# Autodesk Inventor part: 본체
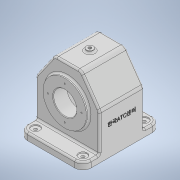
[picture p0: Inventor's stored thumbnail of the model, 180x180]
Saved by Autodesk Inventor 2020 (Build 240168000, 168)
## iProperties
Created: 2022-12
Part Number: 본체
Material: 일반
Document SubType Name: Modeling
Designer: 1강의실14
Density: 1 g/cm^3
Appearance: 기본값
Mass: 347.033 g
Surface Area: 1065.53 cm^2
Volume: 347.033 cm^3
Author: 1강의실14
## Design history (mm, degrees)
sketch "스케치1"
  geometry: L1 (-55, 67)-(55, 67); L2 (55, 67)-(55, -67); L3 (55, -67)-(-55, -67); L4 (-55, -67)-(-55, 67); L5 (-55, 67)-(55, -67); L6 (55, 67)-(-55, -67); 1 further point
  constraints: 12 end point, 2 midpoint, 2 parallel, 1 horizontal, 1 perpendicular
  dimensions: "d0" = 110 distance of L2.end L3.end; "d1" = 134 distance of L1.end L2.end
extrude "돌출1" new body sketch "스케치1" distance "d2" = 12; taper "d3" = 0 deg
sketch "스케치2"
  geometry: L1 (-55, 12)-(55, 12) reference; L2 (55, 12)-(-55, 12) reference; L3 (-55, 0)-(55, 0) reference; L4 (23.491, 122)-(55, 77); L5 (55, 77)-(55, 12); L6 (-55, 77)-(-55, 12); L7 (23.491, 122)-(-23.491, 122); L8 (-23.491, 122)-(-55, 77); 2 further points
  constraints: 10 end point, 2 perpendicular, 1 horizontal, 1 horizontal alignment, 1 midpoint
  dimensions: "d8" = 35 deg angle of L4 L5; "d9" = 65 distance of L1.start L6.start; "d10" = 35 deg angle of L6 L8; "d38" = 122 distance between parallel lines of L3 L7
extrude "돌출2" join sketch "스케치2" stored distance "d11" = 77; taper "d12" = 0 deg
fillet "모깎기1" dims "d13" = 14
sketch "스케치3"
  geometry: A1 r 14 centre (-41, -53) between (-55, -53) and (-41, -67) reference; A2 r 14 centre (41, -53) between (41, -67) and (55, -53) reference; A3 r 14 centre (41, 53) between (55, 53) and (41, 67) reference; A4 r 14 centre (-41, 53) between (-41, 67) and (-55, 53) reference; 5 further points
  constraints: 4 coincident
hole "구멍1" sketch "스케치3" at (-41, -53), (41, -53), (41, 53), (-41, 53) diameter "d14" = 5.5; stored, may be unused: countersink angle "d18" = 90 deg, drill point angle "d20" = 118 deg; dims "d15" = 11, "d16" = 15, "d17" = 2, "d19" = 14
sketch "스케치5"
  geometry: L1 (-41, 0)-(41, 0) reference; C1 r 37.5 at (0, 65); 2 further points
  constraints: 1 centre point, 1 midpoint, 1 vertical alignment
  dimensions: "d21" = 37.5 radius of C1; "d22" = 65 distance from line of C1.centre L1
extrude "돌출3" join sketch "스케치5" distance "d23" = 5; taper "d24" = 0 deg
sketch "스케치6"
  geometry: L1 (-41, 0)-(41, 0) reference; C1 r 31 at (0, 65); 2 further points
  constraints: 1 centre point, 1 midpoint, 1 vertical alignment
  dimensions: "d25" = 31 radius of C1; "d26" = 65 distance from line of L1 C1.centre
extrude "돌출4" join sketch "스케치6" distance "d27" = 10; taper "d28" = 0 deg
sketch "스케치7"
  geometry: L1 (102.5, 43.5)-(27.5, 43.5) reference; L2 (102.5, 38.5)-(102.5, 43.5) reference; L3 (34, -48.5)-(96, -48.5) reference; L4 (96, -38.5)-(96, -48.5) reference; L5 (65, 43.5)-(65, -48.5); L6 (0, -53)-(0, 53) reference; L7 (85, 43.5)-(85, 19.5); L8 (85, -33.5)-(85, -48.5); L9 (122, -38.5)-(122, 38.5) reference; L10 (77, -38.5)-(122, -38.5) reference; L11 (122, 38.5)-(77, 38.5) reference; L12 (85, -33.5)-(85, 19.5); 1 further point
  constraints: 8 end point, 2 midpoint, 2 point on line, 1 perpendicular, 1 vertical
  dimensions: "d29" = 65 distance between parallel lines of L6 L5; "d30" = 24 distance of L7.start L7.end; "d31" = 15 distance of L8.start L8.end; "d34" = 40 diameter of L7 L5; "d36" = 40 diameter of L8 L5
revolve "회전1" sketch "스케치7" stored, may be unused: angle "d41" = 90 deg
node "작업 평면1"
sketch "스케치8"
  geometry: L1 (-55, 12)-(55, 12) reference; L2 (-55, 12)-(-55, 77) reference; L3 (-55, 77)-(-23.491, 122) reference; L4 (-23.491, 122)-(23.491, 122) reference; L5 (23.491, 122)-(55, 77) reference; L6 (55, 77)-(55, 12) reference; L7 (20.888, 117)-(-20.888, 117); L8 (-20.888, 117)-(-50, 75.424); L9 (-50, 75.424)-(-50, 17); L10 (-50, 17)-(50, 17); L11 (50, 17)-(50, 75.424); L12 (50, 75.424)-(20.888, 117); L13 (41, 0)-(-41, 0) reference; L14 (55, 0)-(41, 0) reference; L15 (-41, 0)-(-55, 0) reference; L16 (-50, 17)-(-50, 0); L17 (50, 17)-(50, 0); C1 r 37.5 at (0, 65) reference; 1 further point
  constraints: 16 end point, 2 point on line, 1 parallel, 1 vertical, 5 other
  dimensions: "d43" = 5 distance between parallel lines of L4 L7
extrude "돌출5" cut sketch "스케치8" distance "d44" = 67; taper "d45" = 0 deg
sketch "스케치9"
  geometry: L1 (65, 33.5)-(65, -33.5); L2 (0, -33.5)-(0, 33.5) reference; L3 (45, 33.5)-(85, 33.5) reference; L4 (146.4, -33.5)-(-24.4, -33.5) reference; L5 (65, 19.5)-(38, 19.5); L6 (38, 19.5)-(24, 33.5); L7 (75.424, 33.5)-(0, 33.5) reference; L8 (45, 43.5)-(85, 43.5) reference; 1 further point
  constraints: 6 end point, 3 point on line, 1 perpendicular, 1 vertical
  dimensions: "d46" = 65 distance between parallel lines of L2 L1; "d47" = 135 deg angle of L7 L6; "d48" = 24 distance between parallel lines of L8 L5; "d49" = 54 diameter of L5.end L1
revolve "회전2" sketch "스케치9" stored, may be unused: angle "d50" = 90 deg
sketch "스케치10"
  geometry: C1 r 20 at (0, 0) reference; 1 further point
extrude "돌출6" cut sketch "스케치10" distance "d51" = 67; taper "d52" = 0 deg
chamfer "모따기1" distance "d53" = 1; stored, may be unused: second distance "d54" = 2, angle "d55" = 45 deg
chamfer "모따기2" distance "d56" = 1; stored, may be unused: second distance "d57" = 2, angle "d58" = 45 deg
node "작업 평면2"
sketch "스케치12"
  geometry: L1 (-55, -38.5)-(-55, 38.5) reference; L2 (23.491, 38.5)-(-23.491, 38.5) reference; C1 r 6 at (0, 0); 1 further point
  constraints: 1 centre point
  dimensions: "d62" = 6 radius of C1; "d63" = 55 distance from line of L1 C1.centre; "d64" = 38.5 distance from line of L2 C1.centre
extrude "돌출7" join sketch "스케치12" stored distance "d65" = 67; taper "d66" = 0 deg
sketch "스케치13"
  geometry: C1 r 6 at (0, 0) reference; 2 further points
  constraints: 1 coincident
hole "구멍2" sketch "스케치13" at (0, 0) diameter "d67" = 5.1881; stored, may be unused: countersink angle "d71" = 90 deg, drill point angle "d73" = 118 deg; dims "d68" = 12, "d69" = 15, "d70" = 2, "d72" = 16
fillet "모깎기2" dims "d74" = 3
fillet "모깎기3" dims "d75" = 10
sketch "스케치15" dims "d77" = 29
  geometry: L1 (0, 0)-(0, 29); C1 r 37.5 at (0, 0) reference; 2 further points
  constraints: 2 coincident, 2 end point, 1 vertical, 1 vertical alignment, 2 other
hole "구멍3" sketch "스케치15" at (0, 29) diameter "d78" = 2.459; stored, may be unused: countersink angle "d82" = 90 deg, drill point angle "d84" = 118 deg; dims "d79" = 6, "d80" = 15, "d81" = 2, "d83" = 8
sketch "스케치16" dims "d88" = 26
  geometry: L1 (0, 0)-(0, 26); C1 r 31 at (0, 0) reference; 2 further points
  constraints: 2 coincident, 2 end point, 1 vertical, 1 vertical alignment, 2 other
hole "구멍4" sketch "스케치16" at (0, 26) diameter "d89" = 2.459; stored, may be unused: countersink angle "d93" = 90 deg, drill point angle "d95" = 118 deg; dims "d90" = 6, "d91" = 15, "d92" = 2, "d94" = 8
fillet "모깎기4" dims "d99" = 3
fillet "모깎기5" dims "d100" = 3
fillet "모깎기6" dims "d101" = 3
sketch "스케치17"
  geometry: L1 (0, 0)-(106, 0) reference; L2 (14.5, 73.847)-(14.5, 15) reference; 2 further points
  constraints: 1 other
  dimensions: "d107" = 50 distance from line of L1 point (53, 50); "d108" = 38.5 distance from line of L2 point (53, 50)
feature "엠보싱1" sketch "스케치17" dims "d109" = 0.5, "d110" = 0
fillet "모깎기9" dims "d111" = 3
fillet "모깎기13" dims "d115" = 3
fillet "모깎기14" dims "d116" = 3
fillet "모깎기15" dims "d117" = 3
node "솔리드1"
pattern_circular "원형 패턴1" dims angle "d86" = 360 deg
pattern_circular "원형 패턴2" dims angle "d97" = 360 deg
node "투영된 루프1"
node "투영된 루프2"
feature "A9D066F2-1C7D-4E18-AEED-F7BC21143FA4" dims "d14" = 5.5, "d15" = 11, "d16" = 15, "d17" = 2, "d18" = 90 deg, "d19" = 14, "d20" = 118 deg
other parameters: "d42" = -5, "d61" = -126
